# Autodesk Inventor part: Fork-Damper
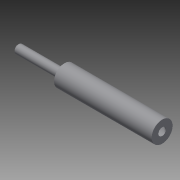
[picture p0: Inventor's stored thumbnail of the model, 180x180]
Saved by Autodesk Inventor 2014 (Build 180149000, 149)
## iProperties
Shininess: 64.0
Length Units: 11272
Angle Units: 11279
Time Units: 11290
Mass Units: 11286
Length Display Precision: 3
Angle Display Precision: 2
Compacted: True
Created: 2001-11
Part Number: Fork-Damper
Document SubType Name: Modeling
Designer: Autodesk, Inc.
Mass: 13.3721 g
Surface Area: 211.026 cm^2
Volume: 13.3721 cm^3
Density: 1 g/cm^3
Material: Generic
Appearance: Default
Density: 0.0
Volumn: 0.0
Area: 0.0
PropertySet Name: Model Information
Control State: 0
Master: False
Checked Out: False
Author: Autodesk, Inc.
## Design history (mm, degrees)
sketch "Sketch1"
  geometry: L1 (32.17, 83.081)-(30.9, 81.811); L2 (85.51, 83.081)-(32.17, 83.081); L3 (85.51, 90.32)-(85.51, 83.081); L4 (199.81, 90.32)-(85.51, 90.32); L5 (199.81, 78.064)-(199.81, 90.32); L6 (30.9, 78.064)-(199.81, 78.064); L7 (30.9, 81.811)-(30.9, 78.064); L8 (30.9, 78.064)-(198.54, 78.064)
  constraints: 16 end point, 3 horizontal, 3 vertical, 1 point on line, 1 other
  dimensions: "d3" = 53.34 distance of L2.start L1.start; "d7" = 114.3 distance of L4.start L3.start
revolve "RevolutionFull1" sketch "Sketch1" stored, may be unused: angle "d8" = 360 deg
shell "Shell1" dims "d9" = 1.27
sketch "Sketch2"
  geometry: C1 r 12.256 at (0, 0) reference
hole "Hole1" sketch "Sketch2" at (0, 0) diameter "d10" = 8.89; stored, may be unused: countersink angle "d14" = 82 deg, drill point angle "d16" = 118 deg; dims "d11" = 12.7, "d12" = 9.525, "d13" = 6.35, "d15" = 19.05
body "Solid1"
other parameters: "d0" = 205.74 (derived), "d2" = 53.34 (derived), "d4" = 38.1 (derived), "d6" = 114.3 (derived)
